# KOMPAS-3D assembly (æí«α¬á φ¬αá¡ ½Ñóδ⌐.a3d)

Referenced files in D:\МОДЕЛЬ ТАНКА Т90\ДЕТАЛИ\КОРПУС\МЕТАЛЛ\КОРПУС ЛИТОЙ\: экран левый.m3d
Referenced files in D:\МОДЕЛЬ ТАНКА Т90\ДЕТАЛИ\ОБЩИЕ ДЕТАЛИ\: шарнир экрана большой.m3d, шарниры ящиков.m3d
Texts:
  Сборка экран левый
